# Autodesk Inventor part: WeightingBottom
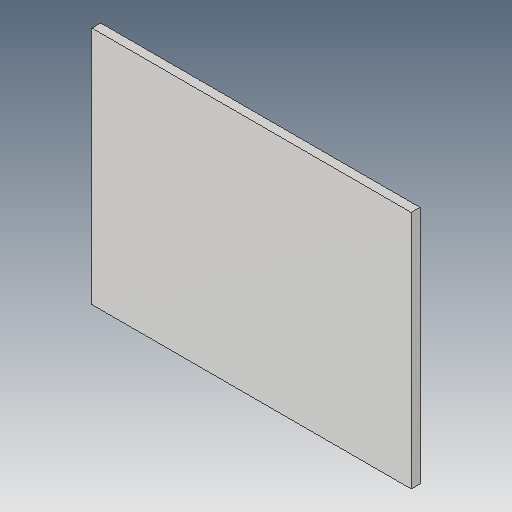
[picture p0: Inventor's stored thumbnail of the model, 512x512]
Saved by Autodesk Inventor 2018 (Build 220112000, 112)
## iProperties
Created: 2018-05
Part Number: WeightingBottom
Material: Generic
Document SubType Name: Modeling
Designer: arivu
Density: 1 g/cm^3
Appearance: Default
Author: arivu
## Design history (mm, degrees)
derived "WaterTank.ipt"
feature "Solid5::WaterTank.ipt" dims "d0" = 10
tag "TaggingFeature1"
body "Solid1"
